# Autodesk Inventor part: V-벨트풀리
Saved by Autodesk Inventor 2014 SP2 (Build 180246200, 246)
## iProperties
Created: 2024-04
Part Number: V-벨트풀리
Material: Generic
Document SubType Name: Modeling
Designer: Administrator
Density: 1 g/cm^3
Appearance: Default
Author: Administrator
Author: jhkim
Creation Date: 2024-04-08
Sending System: Autodesk Inventor 2025
Preprocessor: ST-DEVELOPER v20
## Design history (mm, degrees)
node "V-벨트풀리1"
node "솔리드1"
node "기준1"
